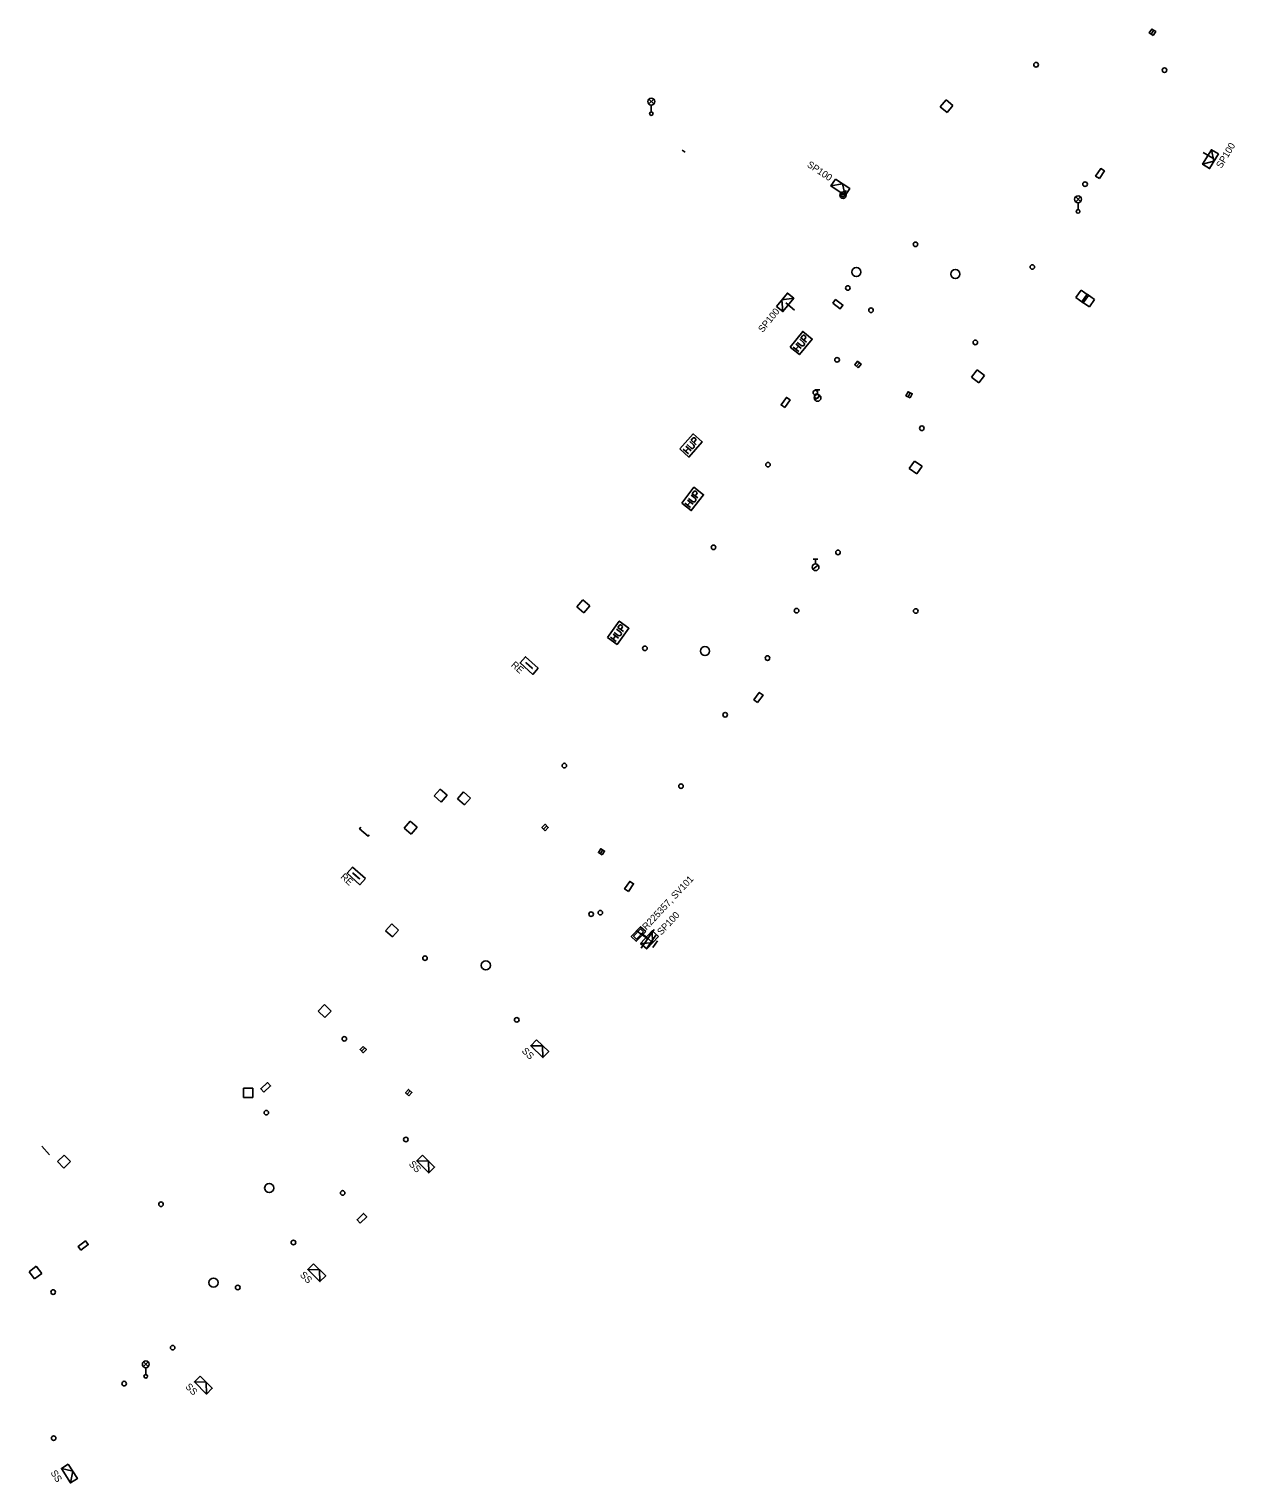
# Model space of a CAD drawing. Extents: x -577028 to -568584, y -1207664 to -1202947.
# Drawn here: x -569133 to -569000.9, y -1204639.5 to -1204480.2 of the extents above; entities that cross this region are included whole.
import ezdxf

# ---------------------------------------------------------------- set-up
doc = ezdxf.new("R2010")
doc.units = 0
for name, color, linetype in [('CIZÍ_NADZEM', 7, 'Continuous'), ('CIZÍ_PODZEM', 7, 'Continuous'), ('ELE_EON', 7, 'Continuous'), ('ELE_EON_POPIS', 7, 'Continuous')]:
    doc.layers.add(name, color=color, linetype=linetype)

msp = doc.modelspace()

# ---------------------------------------------------------------- linework, layer by layer
at = {"layer": 'CIZÍ_NADZEM'}
for p, q in [((-569010.04, -1204480.75), (-569009.76, -1204480.33)), ((-569065.09, -1204488.4), (-569064.57, -1204487.87)), ((-569064.56, -1204488.4), (-569065.09, -1204487.87)), ((-569064.83, -1204488.51), (-569064.83, -1204489.26)), ((-569032.53, -1204487.94), (-569033.17, -1204488.7)), ((-569031.77, -1204488.58), (-569032.53, -1204487.94)), ((-569032.41, -1204489.34), (-569031.77, -1204488.58)), ((-569033.17, -1204488.7), (-569032.41, -1204489.34)), ((-569018.32, -1204499.11), (-569017.8, -1204498.58)), ((-569017.79, -1204499.1), (-569018.32, -1204498.58)), ((-569018.06, -1204499.22), (-569018.06, -1204499.97)), ((-569017.71, -1204508.8), (-569018.3, -1204509.61)), ((-569016.9, -1204509.39), (-569017.71, -1204508.8)), ((-569017.07, -1204509.25), (-569017.63, -1204510.07)), ((-569016.25, -1204509.81), (-569017.07, -1204509.25)), ((-569018.3, -1204509.61), (-569017.49, -1204510.2)), ((-569017.63, -1204510.07), (-569016.81, -1204510.63)), ((-569017.49, -1204510.2), (-569016.9, -1204509.39)), ((-569016.81, -1204510.63), (-569016.25, -1204509.81)), ((-569042.35, -1204517.13), (-569042.03, -1204516.75)), ((-569029.11, -1204517.54), (-569029.72, -1204518.33)), ((-569029.72, -1204518.33), (-569028.93, -1204518.94)), ((-569028.32, -1204518.15), (-569029.11, -1204517.54)), ((-569028.93, -1204518.94), (-569028.32, -1204518.15)), ((-569046.9, -1204520.83), (-569046.31, -1204520.37)), ((-569046.86, -1204519.73), (-569046.36, -1204519.73)), ((-569046.61, -1204520.23), (-569046.61, -1204519.73)), ((-569036.69, -1204520.48), (-569036.47, -1204520.04)), ((-569035.99, -1204527.52), (-569036.56, -1204528.35)), ((-569036.56, -1204528.35), (-569035.73, -1204528.92)), ((-569035.16, -1204528.09), (-569035.99, -1204527.52)), ((-569035.73, -1204528.92), (-569035.16, -1204528.09)), ((-569047.12, -1204539.38), (-569046.53, -1204538.92)), ((-569047.08, -1204538.28), (-569046.58, -1204538.28)), ((-569046.83, -1204538.78), (-569046.83, -1204538.28)), ((-569072.35, -1204542.74), (-569072.98, -1204543.51)), ((-569071.58, -1204543.37), (-569072.35, -1204542.74)), ((-569072.98, -1204543.51), (-569072.21, -1204544.14)), ((-569072.21, -1204544.14), (-569071.58, -1204543.37)), ((-569087.96, -1204563.46), (-569088.63, -1204564.21)), ((-569087.21, -1204564.13), (-569087.96, -1204563.46)), ((-569088.63, -1204564.21), (-569087.88, -1204564.88)), ((-569087.88, -1204564.88), (-569087.21, -1204564.13)), ((-569085.4, -1204563.77), (-569086.07, -1204564.52)), ((-569086.07, -1204564.52), (-569085.32, -1204565.19)), ((-569084.65, -1204564.44), (-569085.4, -1204563.77)), ((-569085.32, -1204565.19), (-569084.65, -1204564.44)), ((-569091.25, -1204566.99), (-569091.91, -1204567.75)), ((-569091.91, -1204567.75), (-569091.15, -1204568.41)), ((-569090.49, -1204567.65), (-569091.25, -1204566.99)), ((-569091.15, -1204568.41), (-569090.49, -1204567.65)), ((-569076.64, -1204567.85), (-569076.3, -1204567.49)), ((-569070.42, -1204570.55), (-569070.16, -1204570.13)), ((-569093.28, -1204578.24), (-569093.95, -1204578.99)), ((-569093.95, -1204578.99), (-569093.2, -1204579.66)), ((-569092.53, -1204578.91), (-569093.28, -1204578.24)), ((-569093.2, -1204579.66), (-569092.53, -1204578.91)), ((-569100.64, -1204587.08), (-569101.34, -1204587.8)), ((-569099.92, -1204587.78), (-569100.64, -1204587.08)), ((-569101.34, -1204587.8), (-569100.62, -1204588.5)), ((-569100.62, -1204588.5), (-569099.92, -1204587.78)), ((-569096.23, -1204591.82), (-569096.59, -1204592.18)), ((-569108.52, -1204596.24), (-569109.52, -1204596.24)), ((-569109.52, -1204596.24), (-569109.52, -1204597.24)), ((-569108.52, -1204597.24), (-569108.52, -1204596.24)), ((-569091.58, -1204596.9), (-569091.26, -1204596.52)), ((-569109.52, -1204597.24), (-569108.52, -1204597.24)), ((-569129.2, -1204603.56), (-569129.92, -1204604.26)), ((-569129.92, -1204604.26), (-569129.22, -1204604.98)), ((-569129.22, -1204604.98), (-569128.5, -1204604.28)), ((-569128.5, -1204604.28), (-569129.2, -1204603.56)), ((-569132.24, -1204615.73), (-569133.03, -1204616.34)), ((-569131.63, -1204616.52), (-569132.24, -1204615.73)), ((-569133.03, -1204616.34), (-569132.42, -1204617.13)), ((-569132.42, -1204617.13), (-569131.63, -1204616.52)), ((-569120.5, -1204626.74), (-569119.98, -1204626.21)), ((-569119.97, -1204626.74), (-569120.5, -1204626.21)), ((-569120.24, -1204626.85), (-569120.24, -1204627.6))]:
    msp.add_line(p, q, dxfattribs=at)
for points in [[(-569009.83, -1204480.89), (-569009.55, -1204480.47), (-569009.97, -1204480.19), (-569010.25, -1204480.61)], [(-569015.72, -1204496.57), (-569015.17, -1204495.74), (-569015.58, -1204495.47), (-569016.13, -1204496.3)], [(-569044.93, -1204510.22), (-569044.13, -1204510.83), (-569043.83, -1204510.44), (-569044.63, -1204509.83)], [(-569042.15, -1204517.29), (-569041.84, -1204516.9), (-569042.23, -1204516.59), (-569042.54, -1204516.98)], [(-569036.47, -1204520.6), (-569036.24, -1204520.15), (-569036.69, -1204519.92), (-569036.92, -1204520.37)], [(-569050.19, -1204521.65), (-569049.62, -1204520.83), (-569050.03, -1204520.55), (-569050.6, -1204521.37)], [(-569053.18, -1204553.97), (-569052.59, -1204553.17), (-569053, -1204552.87), (-569053.59, -1204553.67)], [(-569076.46, -1204568.02), (-569076.12, -1204567.66), (-569076.48, -1204567.32), (-569076.82, -1204567.68)], [(-569070.2, -1204570.68), (-569069.95, -1204570.26), (-569070.37, -1204570), (-569070.63, -1204570.42)], [(-569067.34, -1204574.67), (-569066.78, -1204573.84), (-569067.2, -1204573.57), (-569067.76, -1204574.4)], [(-569096.41, -1204591.65), (-569096.76, -1204592), (-569096.41, -1204592.35), (-569096.06, -1204592)], [(-569107.29, -1204596.67), (-569106.56, -1204595.98), (-569106.91, -1204595.61), (-569107.64, -1204596.3)], [(-569091.39, -1204597.06), (-569091.07, -1204596.69), (-569091.44, -1204596.36), (-569091.77, -1204596.73)], [(-569096.74, -1204611.01), (-569096.02, -1204610.32), (-569096.36, -1204609.95), (-569097.08, -1204610.64)], [(-569127.34, -1204613.98), (-569126.55, -1204613.36), (-569126.86, -1204612.96), (-569127.65, -1204613.58)]]:
    msp.add_lwpolyline(points, close=True, dxfattribs=at)
for points in [[(-569049.62, -1204515.03), (-569048.23, -1204513.32), (-569047.2, -1204514.16), (-569048.6, -1204515.86), (-569049.62, -1204515.03)], [(-569048.43, -1204514.01), (-569048.25, -1204513.79), (-569048.16, -1204513.74), (-569048.12, -1204513.74), (-569048.04, -1204513.76), (-569047.95, -1204513.83), (-569047.92, -1204513.9), (-569047.91, -1204513.95), (-569047.94, -1204514.04), (-569048.12, -1204514.26)], [(-569047.83, -1204514.5), (-569048.43, -1204514.01)], [(-569049.27, -1204515.03), (-569048.67, -1204515.52)], [(-569048.39, -1204515.18), (-569048.99, -1204514.69)], [(-569048.98, -1204515.26), (-569048.71, -1204514.92)], [(-569048.85, -1204514.52), (-569048.42, -1204514.87), (-569048.32, -1204514.91), (-569048.22, -1204514.91), (-569048.13, -1204514.86), (-569048.09, -1204514.81), (-569048.06, -1204514.71), (-569048.08, -1204514.62), (-569048.14, -1204514.53), (-569048.57, -1204514.18)], [(-569061.7, -1204526.2), (-569060.24, -1204524.55), (-569059.25, -1204525.42), (-569060.71, -1204527.08), (-569061.7, -1204526.2)], [(-569060.47, -1204525.23), (-569060.28, -1204525.01), (-569060.2, -1204524.97), (-569060.15, -1204524.97), (-569060.07, -1204524.99), (-569059.99, -1204525.07), (-569059.96, -1204525.14), (-569059.95, -1204525.19), (-569059.98, -1204525.28), (-569060.17, -1204525.49)], [(-569059.9, -1204525.74), (-569060.47, -1204525.23)], [(-569061.35, -1204526.22), (-569060.77, -1204526.73)], [(-569061.07, -1204526.46), (-569060.78, -1204526.13)], [(-569060.48, -1204526.4), (-569061.05, -1204525.89)], [(-569060.91, -1204525.72), (-569060.5, -1204526.09), (-569060.39, -1204526.14), (-569060.29, -1204526.13), (-569060.2, -1204526.09), (-569060.16, -1204526.04), (-569060.13, -1204525.95), (-569060.14, -1204525.85), (-569060.2, -1204525.76), (-569060.62, -1204525.39)], [(-569061.5, -1204532.15), (-569060.16, -1204530.4), (-569059.11, -1204531.21), (-569060.45, -1204532.95), (-569061.5, -1204532.15)], [(-569060.74, -1204531.62), (-569060.31, -1204531.96), (-569060.2, -1204532), (-569060.1, -1204531.99), (-569060.02, -1204531.94), (-569059.98, -1204531.89), (-569059.95, -1204531.79), (-569059.97, -1204531.69), (-569060.04, -1204531.6), (-569060.47, -1204531.27)], [(-569060.34, -1204531.1), (-569060.17, -1204530.87), (-569060.08, -1204530.82), (-569060.03, -1204530.81), (-569059.96, -1204530.83), (-569059.87, -1204530.9), (-569059.83, -1204530.97), (-569059.82, -1204531.02), (-569059.85, -1204531.11), (-569060.02, -1204531.34)], [(-569059.73, -1204531.56), (-569060.34, -1204531.1)], [(-569061.14, -1204532.14), (-569060.53, -1204532.61)], [(-569060.26, -1204532.26), (-569060.88, -1204531.79)], [(-569060.86, -1204532.36), (-569060.59, -1204532.01)], [(-569069.64, -1204546.84), (-569068.35, -1204545.06), (-569067.28, -1204545.84), (-569068.58, -1204547.62), (-569069.64, -1204546.84)], [(-569068.9, -1204546.29), (-569068.46, -1204546.62), (-569068.35, -1204546.66), (-569068.25, -1204546.64), (-569068.17, -1204546.59), (-569068.13, -1204546.54), (-569068.11, -1204546.44), (-569068.13, -1204546.35), (-569068.2, -1204546.26), (-569068.64, -1204545.93)], [(-569068.51, -1204545.76), (-569068.35, -1204545.53), (-569068.26, -1204545.47), (-569068.21, -1204545.47), (-569068.14, -1204545.49), (-569068.05, -1204545.55), (-569068.01, -1204545.62), (-569068, -1204545.67), (-569068.02, -1204545.76), (-569068.19, -1204545.99)], [(-569067.89, -1204546.21), (-569068.51, -1204545.76)], [(-569069.29, -1204546.82), (-569068.67, -1204547.28)], [(-569068.41, -1204546.92), (-569069.03, -1204546.47)], [(-569069, -1204547.04), (-569068.74, -1204546.68)], [(-569096.67, -1204567.65), (-569096.8, -1204567.8), (-569095.88, -1204568.62), (-569095.75, -1204568.47)]]:
    msp.add_lwpolyline(points, dxfattribs=at)
for centre, radius in [((-569022.66, -1204484.1), 0.25), ((-569008.59, -1204484.69), 0.25), ((-569064.83, -1204488.14), 0.375), ((-569064.83, -1204489.46), 0.2), ((-569017.29, -1204497.19), 0.25), ((-569018.06, -1204498.84), 0.375), ((-569018.06, -1204500.17), 0.2), ((-569035.87, -1204503.78), 0.25), ((-569023.07, -1204506.26), 0.25), ((-569042.35, -1204506.81), 0.5), ((-569031.51, -1204507.03), 0.5), ((-569043.29, -1204508.56), 0.25), ((-569040.75, -1204511), 0.25), ((-569029.32, -1204514.52), 0.25), ((-569044.47, -1204516.43), 0.25), ((-569046.86, -1204520.02), 0.25), ((-569046.61, -1204520.6), 0.375), ((-569046.71, -1204520.41), 0.25), ((-569035.18, -1204523.93), 0.25), ((-569052.04, -1204527.92), 0.25), ((-569058.02, -1204536.98), 0.25), ((-569044.37, -1204537.53), 0.25), ((-569046.83, -1204539.15), 0.375), ((-569048.91, -1204543.91), 0.25), ((-569035.85, -1204543.95), 0.25), ((-569065.53, -1204548.04), 0.25), ((-569058.95, -1204548.34), 0.5), ((-569052.09, -1204549.11), 0.25), ((-569056.74, -1204555.32), 0.25), ((-569074.36, -1204560.89), 0.25), ((-569061.58, -1204563.14), 0.25), ((-569071.43, -1204577.16), 0.25), ((-569070.42, -1204577), 0.25), ((-569089.64, -1204581.98), 0.25), ((-569082.97, -1204582.78), 0.5), ((-569079.58, -1204588.75), 0.25), ((-569098.48, -1204590.82), 0.25), ((-569107.03, -1204598.91), 0.25), ((-569091.73, -1204601.85), 0.25), ((-569106.71, -1204607.17), 0.5), ((-569098.66, -1204607.71), 0.25), ((-569118.57, -1204608.95), 0.25), ((-569104.06, -1204613.14), 0.25), ((-569112.82, -1204617.53), 0.5), ((-569130.39, -1204618.57), 0.25), ((-569110.16, -1204618.07), 0.25), ((-569117.29, -1204624.66), 0.25), ((-569120.24, -1204626.48), 0.375), ((-569122.61, -1204628.6), 0.25), ((-569120.24, -1204627.8), 0.2), ((-569130.34, -1204634.58), 0.25)]:
    msp.add_circle(centre, radius, dxfattribs=at)
at = {"layer": 'CIZÍ_PODZEM'}
msp.add_lwpolyline([(-569061.46, -1204493.47), (-569061.13, -1204493.68)], dxfattribs=at)
at = {"layer": 'ELE_EON'}
for p, q in [((-569003.28, -1204494.34), (-569004.34, -1204493.7)), ((-569043.63, -1204498.1), (-569043.49, -1204497.89)), ((-569049.12, -1204510.98), (-569050.08, -1204510.2)), ((-569065.22, -1204579.87), (-569066.46, -1204579.01)), ((-569065.94, -1204580.89), (-569064.51, -1204578.84)), ((-569064.9, -1204580.11), (-569065.82, -1204579.25)), ((-569065.3, -1204580.85), (-569064.33, -1204579.45)), ((-569064.66, -1204580.81), (-569064.15, -1204580.07)), ((-569130.8, -1204603.54), (-569131.62, -1204602.6))]:
    msp.add_line(p, q, dxfattribs=at)
for points in [[(-569002.67, -1204493.87), (-569003.65, -1204495.48), (-569004.42, -1204495.01), (-569003.44, -1204493.41)], [(-569044.64, -1204496.62), (-569043.08, -1204497.66), (-569043.58, -1204498.41), (-569045.14, -1204497.37)], [(-569051.1, -1204510.58), (-569049.92, -1204509.12), (-569049.22, -1204509.69), (-569050.4, -1204511.15)], [(-569077.22, -1204550.21), (-569078.62, -1204548.97), (-569079.22, -1204549.64), (-569077.82, -1204550.89)], [(-569077.86, -1204550.22), (-569078.56, -1204549.6), (-569078.58, -1204549.63), (-569077.88, -1204550.25)], [(-569096.17, -1204573.26), (-569097.57, -1204572.02), (-569098.17, -1204572.69), (-569096.77, -1204573.94)], [(-569096.81, -1204573.27), (-569097.51, -1204572.65), (-569097.53, -1204572.68), (-569096.83, -1204573.3)], [(-569065.45, -1204579.05), (-569066.48, -1204580.14), (-569067.03, -1204579.63), (-569066, -1204578.54)], [(-569065.7, -1204579.09), (-569066.45, -1204579.89), (-569066.78, -1204579.59), (-569066.03, -1204578.78)], [(-569064.06, -1204579.61), (-569065.34, -1204580.98), (-569066, -1204580.37), (-569064.72, -1204578.99)], [(-569077.43, -1204590.93), (-569076.08, -1204592.23), (-569076.71, -1204592.88), (-569078.05, -1204591.58)], [(-569089.91, -1204603.56), (-569088.58, -1204604.88), (-569089.22, -1204605.52), (-569090.54, -1204604.2)], [(-569101.85, -1204615.46), (-569100.52, -1204616.78), (-569101.15, -1204617.42), (-569102.49, -1204616.1)], [(-569114.27, -1204627.78), (-569112.95, -1204629.11), (-569113.59, -1204629.75), (-569114.91, -1204628.41)], [(-569128.73, -1204637.42), (-569127.73, -1204639), (-569128.49, -1204639.48), (-569129.49, -1204637.9)]]:
    msp.add_lwpolyline(points, close=True, dxfattribs=at)
for points in [[(-569003.44, -1204493.41), (-569003.16, -1204494.68), (-569004.42, -1204495.01)], [(-569045.14, -1204497.37), (-569043.86, -1204497.14), (-569043.58, -1204498.41)], [(-569050.4, -1204511.15), (-569050.51, -1204509.85), (-569049.22, -1204509.69)], [(-569064.72, -1204578.99), (-569064.7, -1204580.29), (-569066, -1204580.37)], [(-569078.05, -1204591.58), (-569076.75, -1204591.58), (-569076.71, -1204592.88)], [(-569090.54, -1204604.2), (-569089.24, -1204604.22), (-569089.22, -1204605.52)], [(-569102.49, -1204616.1), (-569101.19, -1204616.12), (-569101.15, -1204617.42)], [(-569114.91, -1204628.41), (-569113.61, -1204628.45), (-569113.59, -1204629.75)], [(-569129.49, -1204637.9), (-569128.23, -1204638.21), (-569128.49, -1204639.48)]]:
    msp.add_lwpolyline(points, dxfattribs=at)
for radius in [0.35, 0.175]:
    msp.add_circle((-569043.82, -1204498.39), radius, dxfattribs=at)

# ---------------------------------------------------------------- texts
at = {"layer": 'ELE_EON_POPIS'}
for s, rotation, p in [('SP100', 58.8186, (-569002.35, -1204495.51)), ('SP100', 326.3259, (-569047.83, -1204495.21)), ('SP100', 50.843, (-569052.62, -1204513.49)), ('RE', 318.3019, (-569080.26, -1204549.94)), ('RE', 318.3231, (-569098.96, -1204573.16)), ('R225357, SV101', 46.9749, (-569065.36, -1204578.96)), ('SP100', 46.9749, (-569063.73, -1204579.52)), ('SS', 315.9864, (-569079.09, -1204592.22)), ('SS', 315.0867, (-569091.46, -1204604.61)), ('SS', 315.2968, (-569103.4, -1204616.75)), ('SS', 314.8017, (-569115.96, -1204629)), ('SS', 302.5048, (-569130.71, -1204638.36))]:
    msp.add_text(s, height=0.75, rotation=rotation, dxfattribs=at).set_placement(p)

doc.saveas('drawing.dxf')
